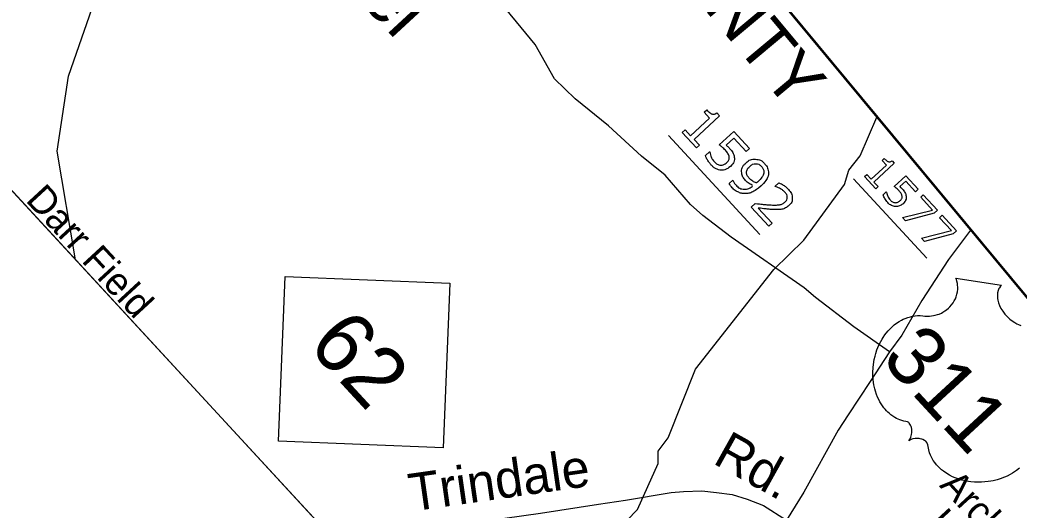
# Model space of a CAD drawing. Extents: x 1695041 to 1706254, y 786537 to 798223.
# Drawn here: x 1703025.1 to 1703274.6, y 796540 to 796662.3 of the extents above; entities that cross this region are included whole.
import ezdxf

# ---------------------------------------------------------------- set-up
doc = ezdxf.new("R2010")
doc.units = 0
for name, color, linetype in [('Default', 7, 'Continuous'), ('Old_Level_29', 7, 'Continuous'), ('Old_Level_30', 7, 'Continuous'), ('Old_Level_32', 7, 'Continuous')]:
    doc.layers.add(name, color=color, linetype=linetype)

msp = doc.modelspace()

# ---------------------------------------------------------------- linework, layer by layer
at = {"layer": 'Default'}
for p, q in [((1702636.99, 797037.98), (1703265.12, 796357.5)), ((1703082.86, 796826.28), (1703289.9, 796576.76)), ((1703187.01, 796633.49), (1703209.85, 796608.75)), ((1703233.23, 796622.65), (1703251.51, 796602.85))]:
    msp.add_line(p, q, dxfattribs=at)
for points in [[(1703207.65, 797564.73), (1702636.99, 797037.98), (1703265.12, 796357.5), (1703835.77, 796884.26)], [(1702807.76, 797162.38), (1703001.1, 796924.8), (1703349.84, 796504.53)], [(1702807.76, 797162.38), (1703001.1, 796924.8), (1703349.84, 796504.53)], [(1703083.28, 796825.8), (1703083.28, 796825.8), (1703172.11, 796719.11), (1703302.41, 796562.08)], [(1703083.28, 796825.8), (1703083.28, 796825.8), (1703172.11, 796719.11), (1703302.41, 796562.08)], [(1703302.56, 796561.89), (1703172.11, 796719.11), (1703083.28, 796825.8)], [(1703302.56, 796561.89), (1703172.11, 796719.11), (1703083.28, 796825.8)], [(1703194.02, 796630.43), (1703190.49, 796634.26), (1703191.21, 796634.92), (1703192.57, 796633.45), (1703197.3, 796637.82), (1703195.94, 796639.29), (1703196.59, 796639.88)], [(1703199.09, 796639.15), (1703199.77, 796638.41), (1703193.41, 796632.54), (1703194.74, 796631.1), (1703194.02, 796630.43)], [(1703199.7, 796631.14), (1703203.34, 796634.5), (1703207.26, 796630.25), (1703206.43, 796629.49), (1703203.35, 796632.82), (1703201.47, 796631.09)], [(1703196.26, 796628.53), (1703197.26, 796629.45), (1703197.32, 796629.39)], [(1703238.83, 796620.21), (1703236.01, 796623.27), (1703236.58, 796623.8), (1703237.67, 796622.62), (1703241.45, 796626.12), (1703240.37, 796627.29), (1703240.89, 796627.77)], [(1703242.89, 796627.18), (1703243.43, 796626.59), (1703238.34, 796621.89), (1703239.41, 796620.74), (1703238.83, 796620.21)], [(1703243.38, 796620.78), (1703246.29, 796623.46), (1703249.42, 796620.06), (1703248.76, 796619.45), (1703246.3, 796622.12), (1703244.79, 796620.74)], [(1703202.18, 796621.53), (1703203.09, 796622.37), (1703203.14, 796622.32)], [(1703213.67, 796620.73), (1703213.63, 796620.78), (1703214.62, 796621.7)], [(1703240.62, 796618.69), (1703241.42, 796619.43), (1703241.47, 796619.37)], [(1703253.39, 796614.07), (1703246.23, 796612.19), (1703245.48, 796613), (1703252.97, 796614.89), (1703250.01, 796618.1), (1703250.67, 796618.71), (1703254.24, 796614.85), (1703253.39, 796614.07)], [(1703212.11, 796610.84), (1703207.69, 796615.62), (1703208.69, 796616.54)], [(1703209.42, 796615.39), (1703212.93, 796611.59), (1703212.11, 796610.84)], [(1703258.12, 796608.95), (1703250.96, 796607.07), (1703250.21, 796607.88), (1703257.69, 796609.77), (1703254.73, 796612.98), (1703255.4, 796613.59), (1703258.96, 796609.73), (1703258.12, 796608.95)], [(1703274.7, 796550.45), (1703273.92, 796549.84), (1703272.95, 796549.2), (1703272.34, 796548.84), (1703271.59, 796548.47), (1703270.92, 796548.17), (1703269.89, 796547.78), (1703269.1, 796547.54), (1703268.14, 796547.3), (1703267.53, 796547.18), (1703266.86, 796547.07), (1703266.07, 796546.98), (1703265.19, 796546.92), (1703264.2, 796546.91), (1703263.44, 796546.94), (1703262.51, 796547.03), (1703261.96, 796547.1), (1703261.22, 796547.24), (1703260.25, 796547.47), (1703259.35, 796547.75), (1703258.62, 796548.02), (1703258, 796548.3), (1703257.24, 796548.68), (1703256.07, 796549.4), (1703255.67, 796549.69), (1703255.22, 796550.05), (1703254.82, 796550.41), (1703254.44, 796550.77), (1703253.97, 796551.28), (1703253.53, 796551.83), (1703253.16, 796552.38), (1703252.8, 796552.98), (1703252.47, 796553.65), (1703252.21, 796554.3), (1703252.01, 796555), (1703251.77, 796556.3), (1703251.67, 796556.65), (1703251.59, 796556.81), (1703251.31, 796557.14), (1703250.97, 796557.38), (1703250.57, 796557.57), (1703250.31, 796557.67), (1703249.92, 796557.76), (1703249.6, 796557.81), (1703249.18, 796557.84), (1703248.85, 796557.83), (1703248.6, 796557.82), (1703248.03, 796557.72), (1703247.78, 796557.64), (1703247.48, 796557.52), (1703247.08, 796557.29), (1703247.4, 796557.78), (1703247.56, 796558.15), (1703247.66, 796558.51), (1703247.74, 796558.85), (1703247.79, 796559.32), (1703247.8, 796559.71), (1703247.77, 796560.15), (1703247.69, 796560.56), (1703247.6, 796560.87), (1703247.49, 796561.14), (1703247.33, 796561.43), (1703247.17, 796561.64), (1703247.02, 796561.8), (1703246.76, 796561.97), (1703246.27, 796562.07), (1703245.82, 796562.17), (1703245.34, 796562.3), (1703244.81, 796562.49), (1703244.43, 796562.64), (1703244.01, 796562.85), (1703243.54, 796563.11), (1703243.06, 796563.42), (1703242.6, 796563.76), (1703242.2, 796564.07), (1703241.8, 796564.43), (1703241.46, 796564.78), (1703241.12, 796565.15), (1703240.83, 796565.52), (1703240.49, 796565.96), (1703240.11, 796566.52), (1703239.82, 796567.02), (1703239.53, 796567.57), (1703239.26, 796568.15), (1703239, 796568.8), (1703238.71, 796569.64), (1703238.54, 796570.25), (1703238.31, 796571.26), (1703238.13, 796572.53), (1703238.06, 796573.54), (1703238.06, 796574.33), (1703238.12, 796575.55), (1703238.19, 796576.3), (1703238.41, 796577.57), (1703238.61, 796578.44), (1703238.78, 796579.05), (1703239.1, 796579.99), (1703239.32, 796580.56), (1703239.68, 796581.34), (1703240.03, 796582.04), (1703240.39, 796582.67), (1703240.63, 796583.05), (1703241.08, 796583.7), (1703241.41, 796584.15), (1703241.89, 796584.73), (1703242.44, 796585.31), (1703242.97, 796585.81), (1703243.42, 796586.21), (1703243.99, 796586.63), (1703244.62, 796587.05), (1703245.19, 796587.38), (1703245.62, 796587.6), (1703246.16, 796587.84), (1703246.79, 796588.08), (1703247.43, 796588.26), (1703247.98, 796588.39), (1703248.61, 796588.49), (1703249.18, 796588.54), (1703249.86, 796588.54), (1703250.52, 796588.5), (1703251.08, 796588.42), (1703251.81, 796588.38), (1703252.22, 796588.39), (1703252.75, 796588.44), (1703253.22, 796588.52), (1703253.62, 796588.61), (1703254.2, 796588.77), (1703254.6, 796588.91), (1703255.18, 796589.17), (1703255.56, 796589.38), (1703256.04, 796589.68), (1703256.46, 796589.97), (1703256.95, 796590.39), (1703257.33, 796590.76), (1703257.74, 796591.24), (1703258.1, 796591.72), (1703258.39, 796592.18), (1703258.67, 796592.75), (1703258.85, 796593.19), (1703259.05, 796593.85), (1703259.2, 796594.5), (1703259.25, 796595.09), (1703259.28, 796595.65), (1703259.24, 796596.14), (1703259.18, 796596.58), (1703259.07, 796597.1), (1703258.94, 796597.57), (1703258.83, 796597.85), (1703270.18, 796596.11), (1703269.93, 796595.84), (1703269.66, 796595.47), (1703269.54, 796595.27), (1703269.36, 796594.82), (1703269.22, 796594.22), (1703269.17, 796593.53), (1703269.21, 796592.84), (1703269.28, 796592.41), (1703269.45, 796591.74), (1703269.71, 796591.03), (1703270.07, 796590.31), (1703270.49, 796589.62), (1703271.01, 796588.92), (1703271.58, 796588.28), (1703272.25, 796587.65), (1703273.09, 796587.03), (1703273.5, 796586.77), (1703273.99, 796586.51), (1703274.47, 796586.28), (1703275.04, 796586.08)]]:
    msp.add_lwpolyline(points, dxfattribs=at)
msp.add_lwpolyline([(1703091.31, 796598.27), (1703132.41, 796596.63), (1703130.76, 796555.52), (1703089.66, 796557.17)], close=True, dxfattribs=at)
for points in [[(1703196.59, 796639.88), (1703196.86, 796639.59), (1703197.23, 796639.29), (1703197.59, 796638.99), (1703197.85, 796638.91), (1703198.17, 796638.8), (1703198.47, 796638.84), (1703198.77, 796638.88), (1703199.09, 796639.15)], [(1703197.32, 796629.39), (1703197.43, 796628.77), (1703197.74, 796628.09), (1703198.05, 796627.41), (1703198.51, 796626.91), (1703198.82, 796626.57), (1703199.21, 796626.34), (1703199.6, 796626.11), (1703200.06, 796626.09), (1703200.46, 796626.07), (1703200.84, 796626.22), (1703201.23, 796626.38), (1703201.6, 796626.73), (1703201.97, 796627.06), (1703202.1, 796627.42), (1703202.24, 796627.78), (1703202.19, 796628.14), (1703202.14, 796628.56), (1703201.89, 796628.98), (1703201.63, 796629.4), (1703201.23, 796629.83), (1703200.85, 796630.25), (1703200.43, 796630.58), (1703200.02, 796630.92), (1703199.7, 796631.14)], [(1703201.47, 796631.09), (1703201.68, 796630.91), (1703201.89, 796630.7), (1703202.09, 796630.5), (1703202.24, 796630.34), (1703202.77, 796629.77), (1703203.07, 796629.24), (1703203.37, 796628.72), (1703203.46, 796628.13), (1703203.55, 796627.51), (1703203.33, 796626.92), (1703203.11, 796626.33), (1703202.48, 796625.76)], [(1703202.48, 796625.76), (1703201.99, 796625.3), (1703201.37, 796625.07), (1703200.76, 796624.83), (1703200.16, 796624.86), (1703199.51, 796624.9), (1703198.9, 796625.2), (1703198.29, 796625.51), (1703197.71, 796626.13), (1703197.18, 796626.71), (1703196.8, 796627.36), (1703196.43, 796628), (1703196.26, 796628.53)], [(1703203.14, 796622.32), (1703203.19, 796622.12), (1703203.36, 796621.81), (1703203.53, 796621.5), (1703203.81, 796621.19), (1703204.78, 796620.14), (1703205.95, 796620.13), (1703207.13, 796620.11), (1703208.32, 796621.04), (1703207.65, 796621.23), (1703207.18, 796621.52), (1703206.71, 796621.8), (1703206.28, 796622.26), (1703205.88, 796622.7), (1703205.64, 796623.13), (1703205.4, 796623.56), (1703205.32, 796624.14), (1703205.22, 796624.83), (1703205.47, 796625.45), (1703205.73, 796626.07), (1703206.35, 796626.65), (1703207.43, 796627.64), (1703208.77, 796627.56), (1703210.1, 796627.48), (1703211.05, 796626.45), (1703211.52, 796625.94), (1703211.76, 796625.36), (1703212.01, 796624.77), (1703211.99, 796624.15), (1703211.97, 796623.39), (1703211.55, 796622.6), (1703211.13, 796621.81), (1703210.15, 796620.9)], [(1703209.47, 796622.05), (1703210.2, 796622.73), (1703210.51, 796623.3), (1703210.82, 796623.86), (1703210.82, 796624.35), (1703210.83, 796624.77), (1703210.68, 796625.11), (1703210.54, 796625.45), (1703210.26, 796625.75), (1703209.63, 796626.43), (1703208.84, 796626.43), (1703208.05, 796626.43), (1703207.28, 796625.72), (1703206.83, 796625.31), (1703206.66, 796624.91), (1703206.49, 796624.52), (1703206.56, 796624.02), (1703206.61, 796623.68), (1703206.8, 796623.37), (1703206.98, 796623.07), (1703207.27, 796622.76), (1703207.61, 796622.39), (1703208.06, 796622.1), (1703208.51, 796621.82), (1703209.01, 796621.66), (1703209.11, 796621.75), (1703209.21, 796621.83), (1703209.32, 796621.91), (1703209.47, 796622.05)], [(1703240.89, 796627.77), (1703241.11, 796627.53), (1703241.4, 796627.29), (1703241.69, 796627.06), (1703241.9, 796626.99), (1703242.15, 796626.9), (1703242.39, 796626.93), (1703242.63, 796626.97), (1703242.89, 796627.18)], [(1703210.15, 796620.9), (1703209.22, 796620.05), (1703208.27, 796619.56), (1703207.33, 796619.07), (1703206.4, 796619.01), (1703205.46, 796618.94), (1703204.57, 796619.32), (1703203.67, 796619.7), (1703202.86, 796620.58), (1703202.63, 796620.82), (1703202.46, 796621.06), (1703202.28, 796621.31), (1703202.18, 796621.53)], [(1703208.69, 796616.54), (1703209.58, 796616.44), (1703210.47, 796616.33), (1703211.36, 796616.22), (1703212.18, 796616.18), (1703213.9, 796616.08), (1703214.73, 796616.22), (1703215.56, 796616.36), (1703216.16, 796616.92), (1703216.71, 796617.42), (1703216.69, 796618.08), (1703216.66, 796618.73), (1703216.06, 796619.38), (1703215.66, 796619.81), (1703215.04, 796620.17), (1703214.43, 796620.54), (1703213.67, 796620.73)], [(1703214.62, 796621.7), (1703215.1, 796621.51), (1703215.76, 796621.08), (1703216.41, 796620.64), (1703216.9, 796620.11), (1703217.9, 796619.03), (1703217.95, 796617.92), (1703217.99, 796616.82), (1703217.1, 796616), (1703216.7, 796615.63), (1703216.25, 796615.41), (1703215.81, 796615.19), (1703215.31, 796615.1), (1703214.85, 796615.01), (1703214.34, 796615), (1703213.82, 796614.98), (1703213.15, 796615.02), (1703212.18, 796615.07), (1703211.22, 796615.18), (1703210.25, 796615.29), (1703209.42, 796615.39)], [(1703241.47, 796619.37), (1703241.56, 796618.88), (1703241.81, 796618.33), (1703242.05, 796617.79), (1703242.43, 796617.39), (1703242.67, 796617.12), (1703242.98, 796616.94), (1703243.29, 796616.75), (1703243.66, 796616.73), (1703243.98, 796616.72), (1703244.29, 796616.84), (1703244.6, 796616.97), (1703244.9, 796617.24), (1703245.19, 796617.51), (1703245.3, 796617.8), (1703245.41, 796618.09), (1703245.36, 796618.38), (1703245.33, 796618.71), (1703245.12, 796619.04), (1703244.92, 796619.38), (1703244.6, 796619.73), (1703244.29, 796620.06), (1703243.96, 796620.33), (1703243.63, 796620.6), (1703243.38, 796620.78)], [(1703244.79, 796620.74), (1703244.96, 796620.59), (1703245.13, 796620.42), (1703245.29, 796620.26), (1703245.41, 796620.13), (1703245.83, 796619.67), (1703246.07, 796619.26), (1703246.31, 796618.84), (1703246.38, 796618.37), (1703246.45, 796617.87), (1703246.28, 796617.4), (1703246.1, 796616.93), (1703245.6, 796616.47)], [(1703245.6, 796616.47), (1703245.21, 796616.11), (1703244.71, 796615.92), (1703244.22, 796615.73), (1703243.74, 796615.75), (1703243.22, 796615.78), (1703242.73, 796616.02), (1703242.24, 796616.27), (1703241.78, 796616.77), (1703241.36, 796617.23), (1703241.06, 796617.75), (1703240.76, 796618.27), (1703240.62, 796618.69)]]:
    msp.add_open_spline(points, degree=3, dxfattribs=at)
at = {"layer": 'Old_Level_29'}
msp.add_lwpolyline([(1703104.13, 796531.91), (1703117.88, 796533.95), (1703133.1, 796536.12), (1703155.07, 796539.16), (1703169.57, 796541.41), (1703176.3, 796542.48), (1703187.74, 796544.39), (1703190.8, 796544.62), (1703195.34, 796544.81), (1703199.04, 796544.37), (1703202.96, 796543.84), (1703206.7, 796542.73), (1703210.79, 796541.08), (1703216.47, 796537.44)], dxfattribs=at)
at = {"layer": 'Old_Level_30'}
for points in [[(1703038.99, 796602.48), (1703034.39, 796629.58), (1703037.18, 796648.35), (1703045.14, 796671.15), (1703038.29, 796687.79), (1703037, 796694.96), (1703037.61, 796706.39), (1703049.65, 796747.44), (1703054.66, 796760.3), (1703090.96, 796816.51)], [(1703150.08, 796482.13), (1703157.83, 796497.33), (1703159.76, 796502.7), (1703171.26, 796531.8), (1703179.26, 796540.13), (1703184.49, 796551.62), (1703184.43, 796554.65), (1703186.95, 796557.98), (1703193.82, 796575.14), (1703213.3, 796600.03), (1703220.8, 796607.33), (1703230.96, 796621.24), (1703232.05, 796624.82), (1703234.9, 796628.46), (1703239.05, 796638.05)]]:
    msp.add_lwpolyline(points, dxfattribs=at)
at = {"layer": 'Old_Level_32'}
for points in [[(1703242.26, 796579.45), (1703233.31, 796585.73), (1703223.73, 796593.02), (1703220.93, 796595.44), (1703202.67, 796608.09), (1703195.64, 796613.52), (1703192.55, 796616.24), (1703186.24, 796623.58), (1703180.26, 796628.34), (1703172.03, 796635.88), (1703163.74, 796642.67), (1703158.54, 796647.67), (1703153.7, 796656.19), (1703142.82, 796669.52)], [(1703262.44, 796609.86), (1703256.99, 796602.55), (1703250.28, 796592.33), (1703245.29, 796583.65), (1703242.26, 796579.45)], [(1703242.26, 796579.45), (1703237.38, 796572.08), (1703231.91, 796563.75), (1703229.44, 796559.92), (1703220.86, 796544.42), (1703216.47, 796537.44)]]:
    msp.add_lwpolyline(points, dxfattribs=at)

# ---------------------------------------------------------------- texts
at = {"layer": 'Default'}
for s, height, rotation, p in [('RANDOLPH COUNTY', 12.6, 309.8165, (1703108.83, 796769.51)), ('Hope Chapel', 13.102, 312.7091, (1703049.6, 796732.36)), ('Darr Field', 6.93, 312.7091, (1703026.28, 796617.25)), ('62', 15.286, 312.7091, (1703096.63, 796580.94)), ('311', 14.849, 312.7091, (1703239.86, 796577.51)), ('Rd.', 9.408, 330.8394, (1703197.81, 796551.79)), ('Trindale', 9.408, 8.1686, (1703122.87, 796539.6)), ('Archdale', 6.93, 312.7091, (1703254.51, 796545.99)), ('United ', 6.93, 312.7091, (1703251.45, 796536.31))]:
    msp.add_text(s, height=height, rotation=rotation, dxfattribs=at).set_placement(p)

doc.saveas('drawing.dxf')
